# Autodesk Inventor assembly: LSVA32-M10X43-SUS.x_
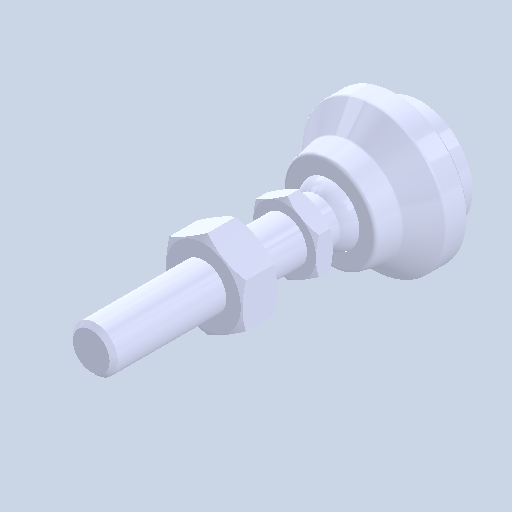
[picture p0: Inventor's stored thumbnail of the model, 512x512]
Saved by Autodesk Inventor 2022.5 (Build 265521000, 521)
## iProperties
Created: 2024-08
Part Number: LSVA32-M10X43-SUS.x_
Document SubType Name: Assembly
Designer: ImaoCorp
Author: ImaoCorp
Sending System: SOLIDWORKS 2022-2022290
MC: AMD64
MC_MODEL: Intel64 Family 6 Model 60 Stepping 3, GenuineIntel
OS: Windows_NT
FRU: Parasolid Version 33.1, build 260,  4-25-2022
FORMAT: text
GUISE: transmit
KEY: FILELSVA32-M10X43-SUS.x_t
DATE: Fri Aug 23 16:06:22 2024
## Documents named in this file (4)
- X:\14_SW2022-Inv2022\06_2024-10新製品(SME)\ELS_データ\l\lsva32-m10x43-sus\LSVA32-M10X43-SUS.x_.iam
- X:\14_SW2022-Inv2022\06_2024-10新製品(SME)\ELS_データ\l\lsva32-m10x43-sus\LSVA32-M10X43-SUS_01.ipt
- X:\14_SW2022-Inv2022\06_2024-10新製品(SME)\ELS_データ\l\lsva32-m10x43-sus\LSVA32-M10X43-SUS_02.ipt
- X:\14_SW2022-Inv2022\06_2024-10新製品(SME)\ELS_データ\l\lsva32-m10x43-sus\LSVA32-M10X43-SUS_03.ipt
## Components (3 placed, 3 different names)
1. LSVA32-M10X43-SUS_01
2. LSVA32-M10X43-SUS_02
3. LSVA32-M10X43-SUS_03
